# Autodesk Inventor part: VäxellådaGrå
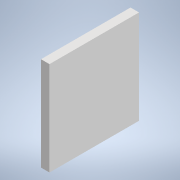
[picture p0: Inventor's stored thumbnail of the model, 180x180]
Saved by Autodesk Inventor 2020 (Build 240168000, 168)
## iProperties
Created: 2019-07
Part Number: VäxellådaGrå
Material: Aluminum 6061, Welded
Document SubType Name: Modeling
Designer: cl
Density: 2.7 g/cm^3
Appearance: Weld - Aluminum
Author: cl
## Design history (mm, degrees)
sketch "Sketch1"
  geometry: L1 (0, 0)-(110, 0); L2 (110, 0)-(110, -105); L3 (110, -105)-(0, -105); L4 (0, -105)-(0, 0)
  constraints: 8 end point, 2 parallel, 1 horizontal, 1 perpendicular
  dimensions: "d0" = 110 distance of L2.end L3.end; "d1" = 105 distance of L1.end L2.end
extrude "Extrusion1" new body sketch "Sketch1" distance "d2" = 100; taper "d3" = 0 deg
fillet "Fillet1" dims "d4" = 5
body "Solid1"
